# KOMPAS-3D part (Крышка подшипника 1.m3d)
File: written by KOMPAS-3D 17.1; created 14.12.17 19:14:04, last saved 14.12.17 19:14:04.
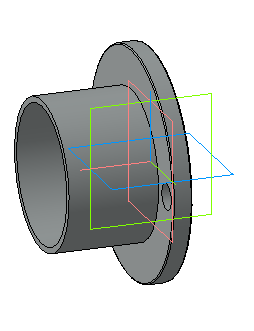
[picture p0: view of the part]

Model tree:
1. Операция без истории:1  (labels: Крышка подшипника 1)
